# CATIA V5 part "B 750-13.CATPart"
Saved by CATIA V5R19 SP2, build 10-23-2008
Part number: B 750-13
Bounding box of the stored display mesh (mm): x -22.494 to 22.494, y -22.494 to 22.494, z 0 to 110.4
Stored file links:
  C:\Users\Bora\Desktop\3D Katı model\B serisi\B 750\B 750-13.CATPart
  C:\Program Files\Dassault Systemes\B19\intel_a\reffiles\standard\MetricThickPitch.txt
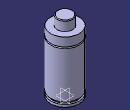
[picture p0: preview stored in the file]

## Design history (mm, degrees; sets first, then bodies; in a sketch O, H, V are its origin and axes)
Body1 (main body)
  Sketch1 on yz-plane, origin (0, 0, 0), H (0, 1, 0), V (0, 0, 1)
    point P1 (22.5, 81.9)
    point P4 (22.5, 79.9)
    point P7 (22.5, 81.9)
    point P8 (22.5, 79.9)
    point P9 (12, 109.4)
    point P11 (12, 109.4)
    line L1 (22.5, 81.9) -> (22.5, 95.4)
    line L2 (22.5, 7.5) -> (22.5, 79.9)
    line L3 (20, 7.5) -> (20, 4)
    arc A1 centre (22.5, 80.9) radius 1 from (22.5, 81.9) to (22.5, 79.9) ccw
    arc A2 centre (11, 109.4) radius 1 from (12, 109.4) to (11, 110.4) ccw
    line L4 (12, 109.4) -> (12, 95.4)
    line L5 (22.5, 0) -> (22.5, 4)
    line L6 (11, 110.4) -> (0, 110.4)
    point P15 (0, 110.4)
    line L7 (12, 95.4) -> (22.5, 95.4)
    line L8 (0, 0) -> (22.5, 0)
    line L9 (20, 7.5) -> (22.5, 7.5)
    line L10 (20, 4) -> (22.5, 4)
    coincidence: P15 V, P1 P7, P4 P8, P9 P11
    tangency: L6 A2
    horizontal: L7 H, L8 H, L9 H, L10 H
  Shaft1: profile Sketch1, axis Sketch1.V, angle 360
  Sketch2 on face of Shaft1 from Sketch1.L8, origin (0, 0, 0), H (1, 0, 0), V (0, -1, 0)
    point P1 (10, 0)
    distance P1 V = 10
  Hole1: placed by Sketch2, at (10, 0, 0) direction (0, 0, 1), diameter 6.647, depth 13, threaded "M8", thread diameter 8, thread depth 13, pitch 1.25
  CircPattern1: of Hole1, instances 2, angular step 180, axis from xy-plane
